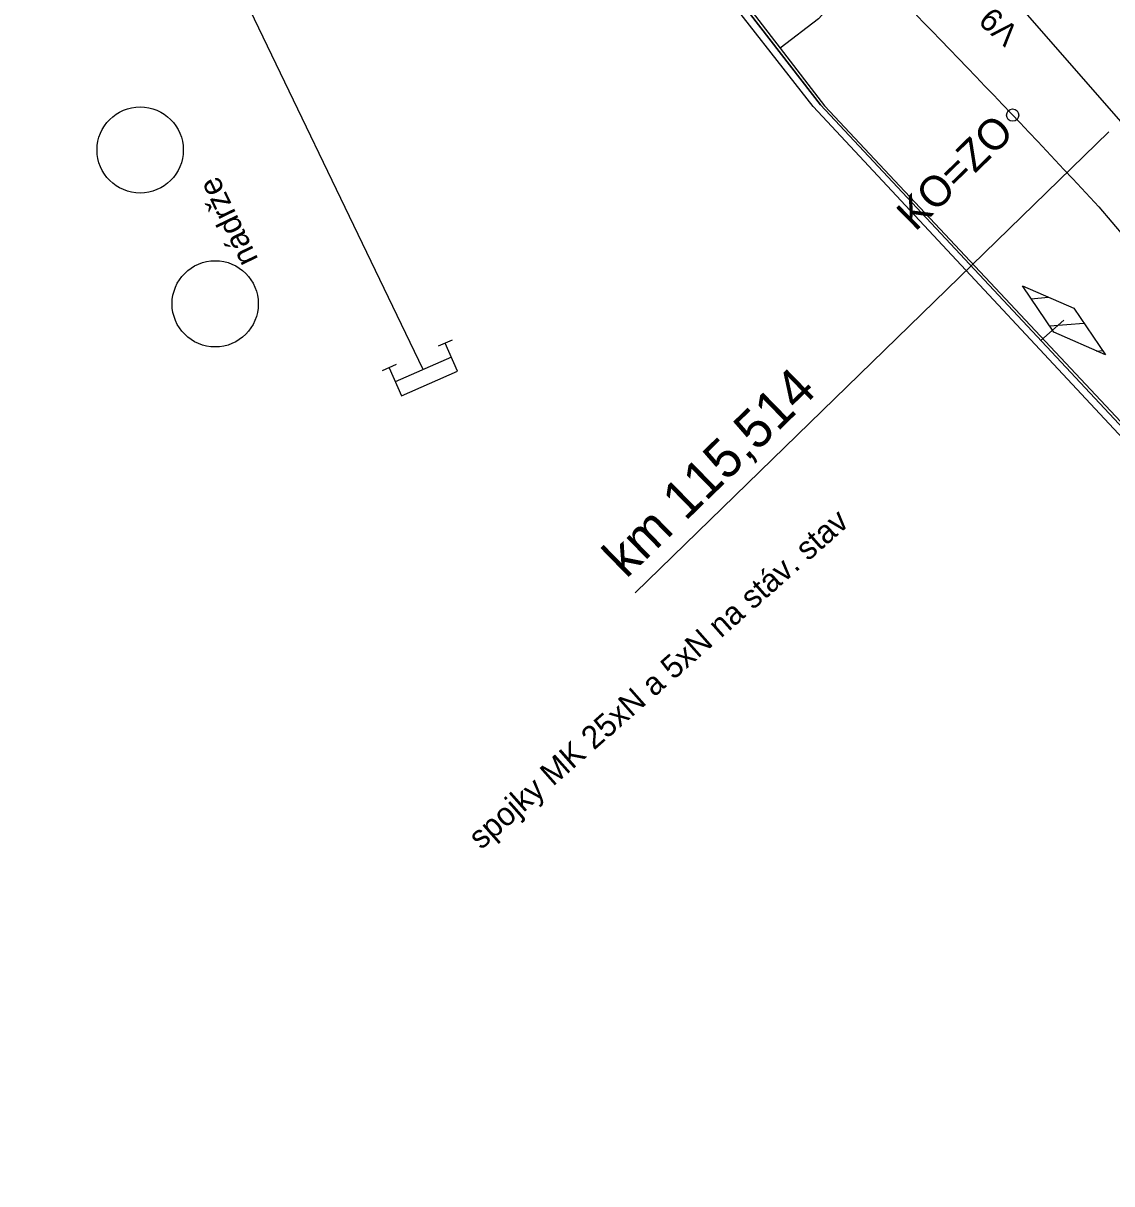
# Model space of a CAD drawing. Extents: x -496570 to -495506, y -1089156 to -1088046.
# Drawn here: x -495946.2 to -495875.3, y -1088785.1 to -1088709.5 of the extents above; entities that cross this region are included whole.
import ezdxf

# ---------------------------------------------------------------- set-up
doc = ezdxf.new("R2010")
doc.units = 0
for name, color, linetype in [('14', 7, 'Continuous'), ('15', 7, 'Continuous'), ('27', 7, 'Continuous'), ('35', 7, 'Continuous'), ('39', 7, 'Continuous'), ('54', 7, 'Continuous'), ('SEE', 7, 'Continuous')]:
    doc.layers.add(name, color=color, linetype=linetype)

msp = doc.modelspace()

# ---------------------------------------------------------------- linework, layer by layer
at = {"layer": '14'}
msp.add_line((-495876.124, -1088721.421), (-495860.222, -1088740.259), dxfattribs=at)
msp.add_lwpolyline([(-495920.141, -1088732.033), (-495934.255, -1088702.718), (-495935.575, -1088699.985), (-495939.964, -1088690.857)], dxfattribs=at)
msp.add_circle((-495881.737, -1088715.451), 0.4, dxfattribs=at)
msp.add_ellipse((-496469.42, -1089273.532), major_axis=(798.669, -137.95), ratio=0.999908, start_param=0.920538, end_param=0.986213, dxfattribs=at)
at = {"layer": '27'}
msp.add_line((-495906.326, -1088746.591), (-495875.462, -1088716.542), dxfattribs=at)
msp.add_lwpolyline([(-495884.123, -1088705.091), (-495873.19, -1088717.6), (-495862.268, -1088730.126)], dxfattribs=at)
at = {"layer": '35'}
for p, q in [((-495918.251, -1088730.114), (-495919.167, -1088730.515)), ((-495918.309, -1088731.231), (-495921.973, -1088732.835)), ((-495921.916, -1088731.718), (-495922.832, -1088732.118))]:
    msp.add_line(p, q, dxfattribs=at)
msp.add_lwpolyline([(-495922.374, -1088731.919), (-495921.572, -1088733.751), (-495917.908, -1088732.147), (-495918.71, -1088730.315)], dxfattribs=at)
at = {"layer": '39'}
for centre in [(-495938.591, -1088717.723), (-495933.701, -1088727.755)]:
    msp.add_circle(centre, 2.81, dxfattribs=at)
at = {"layer": '54'}
for points in [[(-495969.086, -1088638.597), (-495966.23, -1088641.05), (-495951.776, -1088656.491), (-495936.467, -1088670.11), (-495926.204, -1088679.924), (-495906.892, -1088698.439), (-495894.264, -1088714.786), (-495868.546, -1088742.283), (-495860.148, -1088746.773), (-495854.533, -1088753.524)], [(-495951.647, -1088656.374), (-495945.893, -1088661.488), (-495936.346, -1088669.973), (-495925.773, -1088680.163), (-495906.553, -1088698.536), (-495896.884, -1088711.088), (-495893.995, -1088714.839), (-495868.155, -1088742.416), (-495860.018, -1088746.657), (-495854.533, -1088753.524), (-495845, -1088746.917), (-495841.548, -1088746.404), (-495840.19, -1088746.67), (-495839.894, -1088747.064), (-495839.734, -1088747.366), (-495839.482, -1088747.646), (-495839.66, -1088747.957), (-495839.679, -1088748.032), (-495838.294, -1088748.402), (-495823.909, -1088760.307), (-495810.91, -1088770.79), (-495804.093, -1088777.585), (-495801.02, -1088780.504), (-495790.99, -1088790.03)], [(-495791.286, -1088790.273), (-495804.369, -1088777.872), (-495811.106, -1088771.12), (-495824.244, -1088760.551), (-495840.179, -1088747.357), (-495841.548, -1088746.404), (-495845, -1088746.917), (-495854.533, -1088753.524), (-495860.828, -1088746.983), (-495869.129, -1088742.363), (-495894.734, -1088714.89), (-495907.733, -1088698.276), (-495926.154, -1088680.584), (-495936.743, -1088670.436), (-495952.112, -1088656.757)], [(-495890.28, -1088701.16), (-495889.7, -1088701.57), (-495889.79, -1088701.73), (-495890.71, -1088702.45), (-495889.22, -1088703.95), (-495889.32, -1088704.14), (-495892.9, -1088707.51), (-495894.39, -1088709.17), (-495896.884, -1088711.088)]]:
    msp.add_lwpolyline(points, dxfattribs=at)
at = {"layer": 'SEE'}
for p, q in [((-495880.538, -1088727.423), (-495879.413, -1088727.322)), ((-495878.399, -1088728.83), (-495879.898, -1088730.146)), ((-495879.32, -1088729.197), (-495877.092, -1088729.022)), ((-495876.284, -1088730.832), (-495875.872, -1088730.795))]:
    msp.add_line(p, q, dxfattribs=at)
msp.add_lwpolyline([(-495845, -1088746.917), (-495854.533, -1088753.524), (-495860.148, -1088746.773), (-495868.546, -1088742.283), (-495894.264, -1088714.786), (-495906.892, -1088698.439), (-495912.357, -1088693.808), (-495926.204, -1088679.924), (-495936.467, -1088670.11), (-495951.776, -1088656.491), (-495966.23, -1088641.05), (-495966.883, -1088640.489), (-495967.344, -1088640.093), (-495969.086, -1088638.597), (-495972.985, -1088642.454), (-495974.115, -1088643.402), (-495975.48, -1088645.263)], dxfattribs=at)
msp.add_lwpolyline([(-495881.105, -1088726.572), (-495877.747, -1088728.048), (-495875.693, -1088731.088), (-495879.051, -1088729.612)], close=True, dxfattribs=at)

# ---------------------------------------------------------------- texts
at = {"layer": '14'}
msp.add_text('KO=ZO', height=2, rotation=44.42624, dxfattribs=at).set_placement((-495888.077, -1088723.086))
at = {"layer": '15'}
msp.add_text('V9', height=1.5, rotation=137.83154, dxfattribs=at).set_placement((-495881.223, -1088709.96))
at = {"layer": '27'}
msp.add_text('km 115,514', height=2.5, rotation=44.23511, dxfattribs=at).set_placement((-495906.922, -1088745.718))
at = {"layer": '39'}
msp.add_text('nádrže', height=1.5, rotation=115.76332, dxfattribs=at).set_placement((-495930.872, -1088724.852))
at = {"layer": 'SEE'}
msp.add_text('spojky MK 25xN a 5xN na stáv. stav ', height=1.5, rotation=41.44671, dxfattribs=at).set_placement((-495916.376, -1088763.381))

doc.saveas('drawing.dxf')
